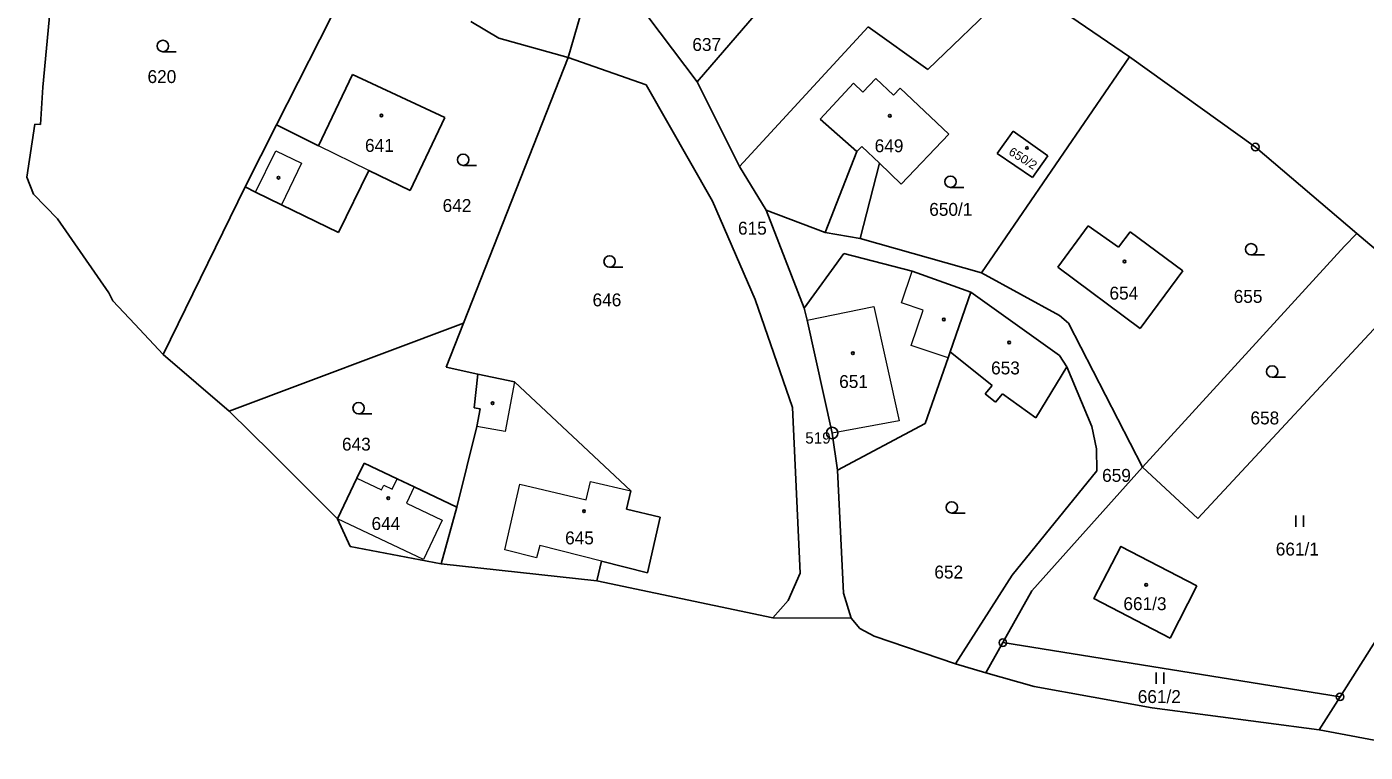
# Model space of a CAD drawing. Extents: x -727701 to -724405, y -960481 to -957284.
# Drawn here: x -726527.5 to -726351.1, y -958792.4 to -958696.7 of the extents above; entities that cross this region are included whole.
import ezdxf
from ezdxf.enums import TextEntityAlignment as Align

# ---------------------------------------------------------------- set-up
doc = ezdxf.new("R2010")
doc.units = 0
doc.header["$LTSCALE"] = 0.68
for name, color, linetype, lineweight in [('1', 7, 'Continuous', 25), ('3', 7, 'Continuous', 25), ('4', 7, 'Continuous', 13), ('5', 7, 'Continuous', 25), ('8', 7, 'Continuous', 25)]:
    doc.layers.add(name, color=color, linetype=linetype, lineweight=lineweight)
doc.layers.add('2', color=7, linetype='Continuous')

msp = doc.modelspace()

# ---------------------------------------------------------------- linework, layer by layer
at = {"layer": '1'}
for p, q in [((-726477.83, -958676.55), (-726494.62, -958709.69)), ((-726408.75, -958702.4), (-726396.68, -958690.79)), ((-726382.12, -958700.72), (-726396.68, -958690.79)), ((-726525.44, -958704.69), (-726524.46, -958694.41)), ((-726456.15, -958700.78), (-726454.08, -958693.7)), ((-726439.13, -958704.01), (-726430.53, -958694.04)), ((-726469, -958696.05), (-726465.31, -958698.25)), ((-726445.63, -958695.41), (-726439.13, -958704.01)), ((-726433.56, -958715.16), (-726416.6, -958696.75)), ((-726416.6, -958696.75), (-726408.75, -958702.4)), ((-726465.31, -958698.25), (-726456.15, -958700.78)), ((-726469.96, -958735.8), (-726456.15, -958700.78)), ((-726445.85, -958704.42), (-726456.15, -958700.78)), ((-726401.64, -958729.2), (-726382.12, -958700.72)), ((-726382.12, -958700.72), (-726365.54, -958712.61)), ((-726489.07, -958712.46), (-726484.57, -958703.05)), ((-726472.41, -958708.72), (-726484.57, -958703.05)), ((-726525.75, -958709.63), (-726525.44, -958704.69)), ((-726437.12, -958719.72), (-726445.85, -958704.42)), ((-726439.13, -958704.01), (-726433.56, -958715.16)), ((-726418.53, -958704.17), (-726422.94, -958708.91)), ((-726417.28, -958705.35), (-726418.53, -958704.17)), ((-726415.58, -958703.58), (-726417.28, -958705.35)), ((-726413.27, -958705.78), (-726415.58, -958703.58)), ((-726412.36, -958704.84), (-726413.27, -958705.78)), ((-726405.98, -958710.91), (-726412.36, -958704.84)), ((-726526.47, -958709.57), (-726527.54, -958716.58)), ((-726525.75, -958709.63), (-726526.47, -958709.57)), ((-726494.62, -958709.69), (-726498.76, -958717.86)), ((-726489.07, -958712.46), (-726494.62, -958709.69)), ((-726476.99, -958718.34), (-726472.41, -958708.72)), ((-726422.94, -958708.91), (-726418.09, -958713.19)), ((-726412.24, -958717.48), (-726405.98, -958710.91)), ((-726397.49, -958710.5), (-726399.57, -958713.45)), ((-726392.89, -958713.74), (-726397.49, -958710.5)), ((-726418.09, -958713.19), (-726422.25, -958723.88)), ((-726399.57, -958713.45), (-726394.95, -958716.61)), ((-726394.95, -958716.61), (-726392.89, -958713.74)), ((-726365.54, -958712.61), (-726352.17, -958723.98)), ((-726486.42, -958723.86), (-726482.44, -958715.69)), ((-726482.44, -958715.69), (-726476.99, -958718.34)), ((-726430.06, -958720.9), (-726433.56, -958715.16)), ((-726417.64, -958724.64), (-726415.11, -958714.73)), ((-726415.11, -958714.73), (-726412.24, -958717.48)), ((-726527.54, -958716.58), (-726526.67, -958718.82)), ((-726526.67, -958718.82), (-726523.49, -958722.05)), ((-726498.76, -958717.86), (-726509.55, -958739.93)), ((-726498.76, -958717.86), (-726497.37, -958718.54)), ((-726497.37, -958718.54), (-726493.96, -958720.2)), ((-726493.96, -958720.2), (-726486.42, -958723.86)), ((-726431.51, -958732.71), (-726437.12, -958719.72)), ((-726430.06, -958720.9), (-726422.25, -958723.88)), ((-726425.02, -958733.84), (-726430.06, -958720.9)), ((-726523.49, -958722.05), (-726516.7, -958731.8)), ((-726422.25, -958723.88), (-726417.64, -958724.64)), ((-726391.61, -958728.45), (-726387.6, -958722.99)), ((-726387.6, -958722.99), (-726383.57, -958725.8)), ((-726383.57, -958725.8), (-726382.05, -958723.76)), ((-726382.05, -958723.76), (-726375.1, -958728.93)), ((-726353.8, -958725.67), (-726352.17, -958723.98)), ((-726352.17, -958723.98), (-726348.47, -958727.13)), ((-726417.64, -958724.64), (-726401.64, -958729.2)), ((-726380.41, -958754.79), (-726353.8, -958725.67)), ((-726419.82, -958726.65), (-726425.02, -958733.84)), ((-726410.78, -958728.96), (-726419.82, -958726.65)), ((-726403.05, -958731.73), (-726410.78, -958728.96)), ((-726391.39, -958734.78), (-726401.64, -958729.2)), ((-726380.75, -958736.53), (-726391.61, -958728.45)), ((-726375.1, -958728.93), (-726380.75, -958736.53)), ((-726516.7, -958731.8), (-726516.18, -958732.85)), ((-726516.18, -958732.85), (-726513.31, -958735.93)), ((-726426.57, -958746.93), (-726431.51, -958732.71)), ((-726403.05, -958731.73), (-726405.79, -958739.57)), ((-726391.38, -958740.06), (-726403.05, -958731.73)), ((-726373.14, -958761.55), (-726346.06, -958732.41)), ((-726424.66, -958735.41), (-726425.02, -958733.84)), ((-726390.19, -958735.81), (-726391.39, -958734.78)), ((-726513.31, -958735.93), (-726509.55, -958739.93)), ((-726500.85, -958747.39), (-726469.96, -958735.8)), ((-726472.25, -958741.61), (-726469.96, -958735.8)), ((-726421.34, -958750.29), (-726424.66, -958735.41)), ((-726380.41, -958754.79), (-726390.19, -958735.81)), ((-726509.55, -958739.93), (-726500.85, -958747.39)), ((-726405.79, -958739.57), (-726400.26, -958744.04)), ((-726390.4, -958741.58), (-726391.38, -958740.06)), ((-726468.07, -958742.52), (-726472.25, -958741.61)), ((-726394.49, -958748.27), (-726390.4, -958741.58)), ((-726387.09, -958749.42), (-726390.4, -958741.58)), ((-726468.56, -958746.95), (-726468.07, -958742.52)), ((-726463.23, -958743.56), (-726468.07, -958742.52)), ((-726447.9, -958757.93), (-726463.23, -958743.56)), ((-726400.26, -958744.04), (-726401.15, -958745.14)), ((-726401.15, -958745.14), (-726399.79, -958746.24)), ((-726399.79, -958746.24), (-726398.9, -958745.14)), ((-726398.9, -958745.14), (-726394.49, -958748.27)), ((-726500.85, -958747.39), (-726495.26, -958752.9)), ((-726467.76, -958747.1), (-726468.56, -958746.95)), ((-726468.19, -958749.41), (-726467.76, -958747.1)), ((-726425.57, -958768.76), (-726426.57, -958746.93)), ((-726420.64, -958755.18), (-726409.1, -958749.05)), ((-726470.84, -958760.06), (-726468.19, -958749.41)), ((-726420.64, -958755.18), (-726421.34, -958750.29)), ((-726386.51, -958752.37), (-726387.09, -958749.42)), ((-726386.46, -958755.27), (-726386.51, -958752.37)), ((-726495.26, -958752.9), (-726486.55, -958761.58)), ((-726484.01, -958756.22), (-726483.07, -958754.25)), ((-726483.07, -958754.25), (-726478.69, -958756.33)), ((-726486.55, -958761.58), (-726484.01, -958756.22)), ((-726419.85, -958771.4), (-726420.64, -958755.18)), ((-726397.63, -958769.04), (-726386.46, -958755.27)), ((-726395.01, -958771.07), (-726380.41, -958754.79)), ((-726380.41, -958754.79), (-726373.14, -958761.55)), ((-726478.69, -958756.33), (-726476.47, -958757.38)), ((-726476.47, -958757.38), (-726470.84, -958760.06)), ((-726448.47, -958760.33), (-726447.9, -958757.93)), ((-726486.55, -958761.58), (-726484.88, -958765.24)), ((-726472.9, -958767.55), (-726470.84, -958760.06)), ((-726444.01, -958761.38), (-726448.47, -958760.33)), ((-726445.7, -958768.72), (-726444.01, -958761.38)), ((-726484.88, -958765.24), (-726472.9, -958767.55)), ((-726472.9, -958767.55), (-726452.36, -958769.76)), ((-726452.36, -958769.76), (-726451.76, -958767.18)), ((-726451.76, -958767.18), (-726445.7, -958768.72)), ((-726452.36, -958769.76), (-726429.16, -958774.66)), ((-726427.14, -958772.37), (-726425.57, -958768.76)), ((-726405.09, -958780.73), (-726397.63, -958769.04)), ((-726418.83, -958774.68), (-726419.85, -958771.4)), ((-726398.84, -958777.92), (-726395.01, -958771.07)), ((-726373.26, -958770.42), (-726376.79, -958777.32)), ((-726429.16, -958774.66), (-726427.14, -958772.37)), ((-726429.16, -958774.66), (-726418.83, -958774.68)), ((-726418.83, -958774.68), (-726417.68, -958776.05)), ((-726417.68, -958776.05), (-726415.81, -958777.07)), ((-726415.81, -958777.07), (-726405.09, -958780.73)), ((-726354.38, -958785.06), (-726348.62, -958775.95)), ((-726401.07, -958781.91), (-726398.84, -958777.92)), ((-726398.84, -958777.92), (-726354.38, -958785.06)), ((-726405.09, -958780.73), (-726401.07, -958781.91)), ((-726401.07, -958781.91), (-726394.73, -958783.69)), ((-726379.16, -958786.5), (-726394.73, -958783.69)), ((-726354.38, -958785.06), (-726357.15, -958789.43)), ((-726379.16, -958786.5), (-726357.15, -958789.43)), ((-726357.15, -958789.43), (-726341.19, -958792.36))]:
    msp.add_line(p, q, dxfattribs=at)
for points in [[(-726405.79, -958739.57), (-726406.07, -958740.38), (-726409.1, -958749.05)], [(-726376.79, -958777.32), (-726386.86, -958772.1), (-726383.27, -958765.24), (-726373.26, -958770.42)]]:
    msp.add_lwpolyline(points, dxfattribs=at)
at = {"layer": '3'}
for p, q in [((-726509.593, -958700.03), (-726507.843, -958700.03)), ((-726470.003, -958715.02), (-726468.253, -958715.02)), ((-726405.743, -958717.92), (-726403.993, -958717.92)), ((-726366.103, -958726.82), (-726364.353, -958726.82)), ((-726450.693, -958728.43), (-726448.943, -958728.43)), ((-726363.323, -958742.94), (-726361.573, -958742.94)), ((-726483.783, -958747.77), (-726482.033, -958747.77)), ((-726405.573, -958760.84), (-726403.823, -958760.84)), ((-726360.211, -958762.65), (-726360.211, -958761.15)), ((-726359.21, -958762.65), (-726359.21, -958761.15)), ((-726378.631, -958783.34), (-726378.631, -958781.84)), ((-726377.63, -958783.34), (-726377.63, -958781.84))]:
    msp.add_line(p, q, dxfattribs=at)
for centre in [(-726509.5929, -958699.2798), (-726470.0029, -958714.2698), (-726405.7429, -958717.1698), (-726366.1029, -958726.0698), (-726450.6929, -958727.6798), (-726363.3229, -958742.1898), (-726483.7829, -958747.0198), (-726405.5729, -958760.0898)]:
    msp.add_circle(centre, 0.75, dxfattribs=at)
at = {"layer": '4'}
for p, q in [((-726497.37, -958718.54), (-726494.72, -958713.09)), ((-726494.72, -958713.09), (-726491.31, -958714.74)), ((-726482.44, -958715.69), (-726489.07, -958712.46)), ((-726417.44, -958712.52), (-726418.09, -958713.19)), ((-726415.11, -958714.73), (-726417.44, -958712.52)), ((-726491.31, -958714.74), (-726493.96, -958720.2)), ((-726412.19, -958733.13), (-726410.78, -958728.96)), ((-726409.34, -958734.09), (-726412.19, -958733.13)), ((-726424.66, -958735.41), (-726415.87, -958733.6)), ((-726415.87, -958733.6), (-726412.5, -958748.69)), ((-726410.91, -958738.75), (-726409.34, -958734.09)), ((-726406.07, -958740.38), (-726410.91, -958738.75)), ((-726463.23, -958743.56), (-726464.46, -958750.11)), ((-726412.5, -958748.69), (-726421.34, -958750.29)), ((-726464.46, -958750.11), (-726468.19, -958749.41)), ((-726484.01, -958756.22), (-726480.76, -958757.77)), ((-726480.76, -958757.77), (-726480.47, -958757.15)), ((-726480.47, -958757.15), (-726479.34, -958757.69)), ((-726479.34, -958757.69), (-726478.69, -958756.33)), ((-726476.47, -958757.38), (-726477.49, -958759.54)), ((-726464.5, -958765.68), (-726462.54, -958757.02)), ((-726462.54, -958757.02), (-726453.76, -958759.08)), ((-726453.76, -958759.08), (-726453.2, -958756.68)), ((-726453.2, -958756.68), (-726447.9, -958757.93)), ((-726477.49, -958759.54), (-726472.78, -958761.78)), ((-726475.23, -958766.95), (-726486.55, -958761.58)), ((-726472.78, -958761.78), (-726475.23, -958766.95)), ((-726459.9, -958765.11), (-726460.31, -958766.73)), ((-726451.76, -958767.18), (-726459.9, -958765.11)), ((-726460.31, -958766.73), (-726464.5, -958765.68))]:
    msp.add_line(p, q, dxfattribs=at)
at = {"layer": '5'}
for centre in [(-726480.7868, -958708.4492), (-726413.7468, -958708.4792), (-726395.6568, -958712.7192), (-726494.3468, -958716.6392), (-726382.7868, -958727.6792), (-726406.6168, -958735.3192), (-726398.0068, -958738.3492), (-726418.6068, -958739.7692), (-726466.1168, -958746.3592), (-726479.8668, -958758.8892), (-726454.0668, -958760.5992), (-726379.9468, -958770.2992)]:
    msp.add_circle(centre, 0.175, dxfattribs=at)
at = {"layer": '8'}
for centre, radius in [((-726365.54, -958712.6099), 0.5), ((-726365.54, -958712.6099), 0.0303), ((-726421.34, -958750.2898), 0.75), ((-726421.34, -958750.2898), 0.03), ((-726398.84, -958777.9199), 0.5), ((-726398.84, -958777.9199), 0.0303), ((-726354.38, -958785.0599), 0.5), ((-726354.38, -958785.0599), 0.0303)]:
    msp.add_circle(centre, radius, dxfattribs=at)

# ---------------------------------------------------------------- texts
at = {"layer": '2'}
for s, p in [('637', (-726439.78, -958699.935)), ('620', (-726511.62, -958704.165)), ('641', (-726482.94, -958713.235)), ('649', (-726415.74, -958713.285)), ('642', (-726472.71, -958721.155)), ('615', (-726433.76, -958724.145)), ('654', (-726384.78, -958732.705)), ('655', (-726368.4, -958733.135)), ('646', (-726452.94, -958733.595)), ('653', (-726400.39, -958742.565)), ('651', (-726420.42, -958744.355)), ('658', (-726366.19, -958749.155)), ('643', (-726485.98, -958752.605)), ('659', (-726385.75, -958756.725)), ('644', (-726482.08, -958763.065)), ('645', (-726456.56, -958764.965)), ('652', (-726407.87, -958769.465))]:
    msp.add_text(s, height=1.7, dxfattribs=at).set_placement(p)
at = {"layer": '2', "width": 1.05}
msp.add_text('650/2', height=1.139, rotation=328, dxfattribs=at).set_placement((-726396.4773, -958714.5767), align=Align.CENTER)
at = {"layer": '2'}
for s, p in [('650/1', (-726405.7, -958721.665)), ('661/1', (-726360.01, -958766.435)), ('661/3', (-726380.1, -958773.635)), ('661/2', (-726378.21, -958785.875))]:
    msp.add_text(s, height=1.7, dxfattribs=at).set_placement(p, align=Align.CENTER)
at = {"layer": '8'}
msp.add_text('519', height=1.5, dxfattribs=at).set_placement((-726424.89, -958751.685))

doc.saveas('drawing.dxf')
